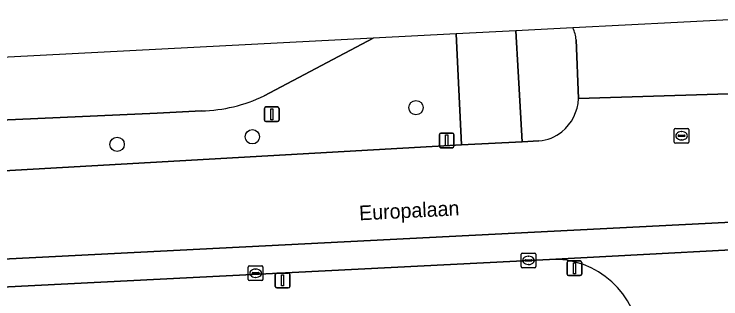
# Model space of a CAD drawing. Extents: x 161248 to 161848, y 384871 to 385383.
# Drawn here: x 161346.09 to 161394.3, y 385339.5 to 385358.92 of the extents above; entities that cross this region are included whole.
import ezdxf

# ---------------------------------------------------------------- set-up
doc = ezdxf.new("R2010")
doc.units = 0
for name, color, linetype in [('IMGEO_Berm_groen', 7, 'Continuous'), ('IMGEO_Boom', 7, 'Continuous'), ('IMGEO_Kolk', 7, 'Continuous'), ('IMGEO_Lichtmast', 7, 'Continuous'), ('IMGEO_Openbare_ruimte_label', 7, 'Continuous'), ('IMGEO_Rijbaan_lokaal_gesloten', 7, 'Continuous'), ('IMGEO_Rijbaan_lokaal_open', 7, 'Continuous'), ('IMGEO_Rioolput', 7, 'Continuous'), ('IMGEO_Verkeersbordpaal', 7, 'Continuous'), ('IMGEO_Verkeerseiland_open', 7, 'Continuous'), ('IMGEO_Voetpad_open', 7, 'Continuous')]:
    doc.layers.add(name, color=color, linetype=linetype)

msp = doc.modelspace()

# ---------------------------------------------------------------- linework, layer by layer
at = {"layer": 'IMGEO_Berm_groen'}
for points in [[(161268.516, 385344.454), (161288.559, 385345.391), (161324.155, 385347.024), (161376.6, 385350.004), (161376.38, 385354.718), (161376.236, 385357.567), (161370.581, 385357.274)], [(161370.581, 385357.274), (161363.136, 385353.342)], [(161358.872, 385352.316), (161355.845, 385352.165), (161324.775, 385350.775), (161310.535, 385350.215), (161285.7, 385348.87), (161268.134, 385347.902)]]:
    msp.add_lwpolyline(points, dxfattribs=at)
msp.add_arc((161358.538, 385363.076), 10.766, 271.7764, 295.2822, dxfattribs=at)
at = {"layer": 'IMGEO_Boom'}
for centre in [(161373.498, 385352.542), (161362.338, 385350.557), (161353.112, 385350.04)]:
    msp.add_circle(centre, 0.489, dxfattribs=at)
at = {"layer": 'IMGEO_Kolk'}
for p, q in [((161380.749, 385342.627), (161381.601, 385342.627)), ((161380.674, 385341.701), (161380.674, 385342.553)), ((161380.933, 385342.121), (161380.933, 385342.133)), ((161380.976, 385342.17), (161381.374, 385342.17)), ((161381.162, 385342.407), (161381.187, 385342.407)), ((161381.417, 385342.133), (161381.417, 385342.121)), ((161381.675, 385342.553), (161381.675, 385341.701)), ((161362.062, 385340.821), (161362.062, 385341.673)), ((161362.137, 385341.747), (161362.989, 385341.747)), ((161363.063, 385341.673), (161363.063, 385340.821)), ((161381.601, 385341.627), (161380.749, 385341.627)), ((161381.371, 385342.084), (161380.973, 385342.084)), ((161381.185, 385341.847), (161381.16, 385341.847)), ((161362.321, 385341.241), (161362.321, 385341.253)), ((161362.759, 385341.204), (161362.361, 385341.204)), ((161362.364, 385341.29), (161362.762, 385341.29)), ((161362.55, 385341.527), (161362.575, 385341.527)), ((161362.805, 385341.253), (161362.805, 385341.241)), ((161362.989, 385340.747), (161362.137, 385340.747)), ((161362.573, 385340.967), (161362.548, 385340.967))]:
    msp.add_line(p, q, dxfattribs=at)
for points in [[(161380.749, 385342.627), (161381.601, 385342.627)], [(161380.674, 385341.701), (161380.674, 385342.553)], [(161381.675, 385342.553), (161381.675, 385341.701)], [(161362.062, 385340.821), (161362.062, 385341.673)], [(161362.137, 385341.747), (161362.989, 385341.747)], [(161363.063, 385341.673), (161363.063, 385340.821)], [(161381.601, 385341.627), (161380.749, 385341.627)], [(161362.989, 385340.747), (161362.137, 385340.747)]]:
    msp.add_lwpolyline(points, dxfattribs=at)
for centre, radius, start, end in [((161380.751, 385342.551), 0.0765, 91.552, 178.448), ((161380.751, 385342.551), 0.0765, 91.552, 178.448), ((161381.599, 385342.551), 0.0765, 1.552, 88.448), ((161381.599, 385342.551), 0.0765, 1.552, 88.448), ((161380.973, 385342.13), 0.0403, 85.8775, 175.7526), ((161380.97, 385342.12), 0.0366, 178.938, 274.7102), ((161381.374, 385342.127), 0.043, 264.8664, 352.4533), ((161381.378, 385342.132), 0.0386, 1.7309, 96.639), ((161362.139, 385341.671), 0.0765, 91.552, 178.448), ((161362.139, 385341.671), 0.0765, 91.552, 178.448), ((161362.987, 385341.671), 0.0765, 1.552, 88.448), ((161362.987, 385341.671), 0.0765, 1.552, 88.448), ((161380.751, 385341.703), 0.0765, 181.552, 268.448), ((161380.751, 385341.703), 0.0765, 181.552, 268.448), ((161381.599, 385341.703), 0.0765, 271.552, 358.448), ((161381.599, 385341.703), 0.0765, 271.552, 358.448), ((161362.361, 385341.25), 0.0403, 85.8775, 175.7526), ((161362.358, 385341.24), 0.0366, 178.938, 274.7102), ((161362.762, 385341.247), 0.043, 264.8664, 352.4533), ((161362.766, 385341.252), 0.0386, 1.7309, 96.639), ((161362.139, 385340.823), 0.0765, 181.552, 268.448), ((161362.139, 385340.823), 0.0765, 181.552, 268.448), ((161362.987, 385340.823), 0.0765, 271.552, 358.448), ((161362.987, 385340.823), 0.0765, 271.552, 358.448)]:
    msp.add_arc(centre, radius, start, end, dxfattribs=at)
for centre, major_axis, ratio, start_param, end_param in [((161381.161, 385342.127), (-0.387, 0.002), 0.722429, 4.712389, 7.853982), ((161381.186, 385342.127), (-0.39, 0.002), 0.717154, 1.570796, 4.712389), ((161362.549, 385341.247), (-0.387, 0.002), 0.722429, 4.712389, 7.853982), ((161362.574, 385341.247), (-0.39, 0.002), 0.717154, 1.570796, 4.712389)]:
    msp.add_ellipse(centre, major_axis=major_axis, ratio=ratio, start_param=start_param, end_param=end_param, dxfattribs=at)
at = {"layer": 'IMGEO_Lichtmast'}
for p, q in [((161383.814, 385341.187), (161383.814, 385341.987)), ((161383.814, 385341.987), (161383.814, 385341.187)), ((161383.914, 385342.087), (161384.704, 385342.087)), ((161384.704, 385342.087), (161383.914, 385342.087)), ((161384.804, 385341.987), (161384.804, 385341.187)), ((161384.804, 385341.187), (161384.804, 385341.987)), ((161363.9, 385340.356), (161363.9, 385341.156)), ((161363.9, 385341.156), (161363.9, 385340.356)), ((161364, 385341.256), (161364.79, 385341.256)), ((161364.79, 385341.256), (161364, 385341.256)), ((161364.89, 385341.156), (161364.89, 385340.356)), ((161364.89, 385340.356), (161364.89, 385341.156)), ((161384.704, 385341.087), (161383.914, 385341.087)), ((161383.914, 385341.087), (161384.704, 385341.087)), ((161364.79, 385340.256), (161364, 385340.256)), ((161364, 385340.256), (161364.79, 385340.256))]:
    msp.add_line(p, q, dxfattribs=at)
for points in [[(161384.234, 385341.962), (161384.384, 385341.962), (161384.384, 385341.212), (161384.234, 385341.212), (161384.234, 385341.962)], [(161364.32, 385341.131), (161364.47, 385341.131), (161364.47, 385340.381), (161364.32, 385340.381), (161364.32, 385341.131)]]:
    msp.add_lwpolyline(points, dxfattribs=at)
for centre, start, end in [((161383.914, 385341.987), 90, 180), ((161383.914, 385341.987), 90, 180), ((161384.704, 385341.987), 0, 90), ((161384.704, 385341.987), 360, 90), ((161364, 385341.156), 90, 180), ((161364, 385341.156), 90, 180), ((161364.79, 385341.156), 0, 90), ((161364.79, 385341.156), 360, 90), ((161383.914, 385341.187), 180, 270), ((161383.914, 385341.187), 180, 270), ((161384.704, 385341.187), 270, 0), ((161384.704, 385341.187), 270, 0), ((161364, 385340.356), 180, 270), ((161364, 385340.356), 180, 270), ((161364.79, 385340.356), 270, 0), ((161364.79, 385340.356), 270, 0)]:
    msp.add_arc(centre, 0.1, start, end, dxfattribs=at)
at = {"layer": 'IMGEO_Rijbaan_lokaal_gesloten'}
for points in [[(161402.333, 385358.921), (161391.347, 385358.351), (161384.19, 385357.98)], [(161363.136, 385353.342), (161370.581, 385357.274), (161310.703, 385354.168), (161252.644, 385354.672)], [(161384.421, 385357.171), (161384.594, 385353.158), (161398.476, 385353.605)], [(161382.607, 385342.195), (161401.421, 385343.184), (161500, 385348.169), (161538.421, 385350.118), (161631.519, 385354.842), (161631.397, 385356.891), (161617.266, 385356.241), (161538.32, 385351.908), (161405.743, 385345.272), (161403.061, 385345.136), (161313.081, 385340.569), (161302.699, 385339.685), (161293.531, 385337.916), (161290.897, 385337.069), (161291.775, 385334.722), (161292.828, 385335.119)], [(161398.476, 385353.605), (161384.594, 385353.158)], [(161254.106, 385347.204), (161261.578, 385347.58), (161261.808, 385347.59), (161264.882, 385347.731), (161268.134, 385347.902), (161285.7, 385348.87), (161310.535, 385350.215), (161324.775, 385350.775), (161355.845, 385352.165), (161358.872, 385352.316)], [(161290.897, 385337.069), (161293.531, 385337.916), (161302.699, 385339.685), (161313.081, 385340.569), (161403.061, 385345.136), (161402.887, 385348.241), (161402.713, 385351.347)], [(161381.89, 385350.269), (161380.733, 385350.21), (161376.6, 385350.004), (161324.155, 385347.024), (161288.559, 385345.391), (161268.516, 385344.454), (161266.956, 385344.394), (161265.291, 385344.323), (161262.15, 385344.152), (161258.577, 385343.968), (161255.028, 385343.811), (161254.449, 385343.782)], [(161304.085, 385337.824), (161305.471, 385337.988), (161309.803, 385338.304), (161313.29, 385338.586), (161317.381, 385338.812), (161325.423, 385339.298), (161382.607, 385342.195)]]:
    msp.add_lwpolyline(points, dxfattribs=at)
for centre, radius, start, end in [((161382.49, 385357.058), 1.935, 3.3544, 28.4605), ((161358.538, 385363.076), 10.766, 271.7764, 295.2822), ((161381.394, 385353.348), 3.206, 310.108, 356.5999), ((161381.572, 385353.34), 3.088, 275.9033, 307.6617)]:
    msp.add_arc(centre, radius, start, end, dxfattribs=at)
at = {"layer": 'IMGEO_Rijbaan_lokaal_open'}
msp.add_lwpolyline([(161401.421, 385343.184), (161382.607, 385342.195)], dxfattribs=at)
msp.add_arc((161382.886, 385336.302), 5.9, 2.9092, 92.7063, dxfattribs=at)
at = {"layer": 'IMGEO_Rioolput'}
for p, q in [((161391.118, 385350.2), (161391.118, 385351.052)), ((161391.193, 385351.126), (161392.045, 385351.126)), ((161391.606, 385350.906), (161391.631, 385350.906)), ((161392.119, 385351.052), (161392.119, 385350.2)), ((161391.377, 385350.62), (161391.377, 385350.632)), ((161391.815, 385350.583), (161391.417, 385350.583)), ((161391.42, 385350.669), (161391.818, 385350.669)), ((161391.629, 385350.346), (161391.604, 385350.346)), ((161391.861, 385350.632), (161391.861, 385350.62)), ((161392.045, 385350.126), (161391.193, 385350.126))]:
    msp.add_line(p, q, dxfattribs=at)
for points in [[(161391.118, 385350.2), (161391.118, 385351.052)], [(161391.193, 385351.126), (161392.045, 385351.126)], [(161392.119, 385351.052), (161392.119, 385350.2)], [(161392.045, 385350.126), (161391.193, 385350.126)]]:
    msp.add_lwpolyline(points, dxfattribs=at)
for centre, radius, start, end in [((161391.195, 385351.05), 0.0765, 91.552, 178.448), ((161391.195, 385351.05), 0.0765, 91.552, 178.448), ((161392.043, 385351.05), 0.0765, 1.552, 88.448), ((161392.043, 385351.05), 0.0765, 1.552, 88.448), ((161391.417, 385350.629), 0.0403, 85.8775, 175.7526), ((161391.414, 385350.619), 0.0366, 178.938, 274.7102), ((161391.818, 385350.626), 0.043, 264.8664, 352.4533), ((161391.822, 385350.631), 0.0386, 1.7309, 96.639), ((161391.195, 385350.202), 0.0765, 181.552, 268.448), ((161391.195, 385350.202), 0.0765, 181.552, 268.448), ((161392.043, 385350.202), 0.0765, 271.552, 358.448), ((161392.043, 385350.202), 0.0765, 271.552, 358.448)]:
    msp.add_arc(centre, radius, start, end, dxfattribs=at)
for centre, major_axis, ratio, start_param, end_param in [((161391.605, 385350.626), (-0.387, 0.002), 0.722429, 4.712389, 7.853982), ((161391.63, 385350.626), (-0.39, 0.002), 0.717154, 1.570796, 4.712389)]:
    msp.add_ellipse(centre, major_axis=major_axis, ratio=ratio, start_param=start_param, end_param=end_param, dxfattribs=at)
at = {"layer": 'IMGEO_Verkeersbordpaal'}
for p, q in [((161363.168, 385351.69), (161363.168, 385352.49)), ((161363.168, 385352.49), (161363.168, 385351.69)), ((161363.268, 385352.59), (161364.058, 385352.59)), ((161364.058, 385352.59), (161363.268, 385352.59)), ((161364.158, 385352.49), (161364.158, 385351.69)), ((161364.158, 385351.69), (161364.158, 385352.49)), ((161364.058, 385351.59), (161363.268, 385351.59)), ((161363.268, 385351.59), (161364.058, 385351.59)), ((161375.201, 385350.808), (161375.991, 385350.808)), ((161375.991, 385350.808), (161375.201, 385350.808)), ((161375.101, 385349.908), (161375.101, 385350.708)), ((161375.101, 385350.708), (161375.101, 385349.908)), ((161376.091, 385350.708), (161376.091, 385349.908)), ((161376.091, 385349.908), (161376.091, 385350.708)), ((161375.991, 385349.808), (161375.201, 385349.808)), ((161375.201, 385349.808), (161375.991, 385349.808))]:
    msp.add_line(p, q, dxfattribs=at)
for points in [[(161363.588, 385352.465), (161363.738, 385352.465), (161363.738, 385351.715), (161363.588, 385351.715), (161363.588, 385352.465)], [(161375.521, 385350.683), (161375.671, 385350.683), (161375.671, 385349.933), (161375.521, 385349.933), (161375.521, 385350.683)]]:
    msp.add_lwpolyline(points, dxfattribs=at)
for centre, start, end in [((161363.268, 385352.49), 90, 180), ((161363.268, 385352.49), 90, 180), ((161364.058, 385352.49), 0, 90), ((161364.058, 385352.49), 360, 90), ((161363.268, 385351.69), 180, 270), ((161363.268, 385351.69), 180, 270), ((161364.058, 385351.69), 270, 0), ((161364.058, 385351.69), 270, 0), ((161375.201, 385350.708), 90, 180), ((161375.201, 385350.708), 90, 180), ((161375.991, 385350.708), 0, 90), ((161375.991, 385350.708), 360, 90), ((161375.201, 385349.908), 180, 270), ((161375.201, 385349.908), 180, 270), ((161375.991, 385349.908), 270, 0), ((161375.991, 385349.908), 270, 0)]:
    msp.add_arc(centre, 0.1, start, end, dxfattribs=at)
at = {"layer": 'IMGEO_Verkeerseiland_open'}
for points in [[(161384.19, 385357.98), (161380.309, 385357.778)], [(161380.309, 385357.778), (161380.48, 385355.008), (161380.733, 385350.21), (161381.89, 385350.269)], [(161384.594, 385353.158), (161384.421, 385357.171)]]:
    msp.add_lwpolyline(points, dxfattribs=at)
for centre, radius, start, end in [((161382.49, 385357.058), 1.935, 3.3544, 28.4605), ((161381.394, 385353.348), 3.206, 310.108, 356.5999), ((161381.572, 385353.34), 3.088, 275.9033, 307.6617)]:
    msp.add_arc(centre, radius, start, end, dxfattribs=at)
at = {"layer": 'IMGEO_Voetpad_open'}
msp.add_lwpolyline([(161376.236, 385357.567), (161376.38, 385354.718), (161376.6, 385350.004), (161380.733, 385350.21), (161380.48, 385355.008), (161380.309, 385357.778)], close=True, dxfattribs=at)
msp.add_lwpolyline([(161382.607, 385342.195), (161325.423, 385339.298), (161317.381, 385338.812), (161313.29, 385338.586), (161309.803, 385338.304), (161305.471, 385337.988), (161304.085, 385337.824)], dxfattribs=at)
msp.add_arc((161382.886, 385336.302), 5.9, 2.9092, 92.7063, dxfattribs=at)

# ---------------------------------------------------------------- texts
at = {"layer": 'IMGEO_Openbare_ruimte_label'}
msp.add_text('Europalaan', height=1, rotation=2.8653, dxfattribs=at).set_placement((161369.645, 385344.857))

doc.saveas('drawing.dxf')
